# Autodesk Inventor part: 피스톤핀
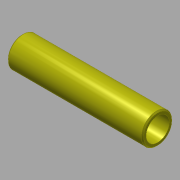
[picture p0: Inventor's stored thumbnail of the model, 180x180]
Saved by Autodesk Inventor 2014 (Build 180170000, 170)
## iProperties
Created: 2016-11
Part Number: 피스톤핀
Material: 강철, 탄소
Document SubType Name: Modeling
Designer: mduedu
Density: 7.87 g/cm^3
Appearance: 노란색
Mass: 24.6584 g
Surface Area: 42.7469 cm^2
Volume: 3.13322 cm^3
Author: mduedu
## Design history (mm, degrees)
sketch "스케치1"
  geometry: C1 r 5 at (0, 0); C2 r 6.5 at (0, 0); 1 further point
  constraints: 2 centre point, 2 coincident
  dimensions: "d0" = 10 diameter of C1; "d1" = 13 diameter of C2
extrude "돌출1" new body sketch "스케치1" stored distance "d2" = 58; taper "d3" = 0 deg
chamfer "모따기1" distance "d4" = 0.5; stored, may be unused: second distance "d5" = 2, angle "d6" = 45 deg
node "솔리드1"
